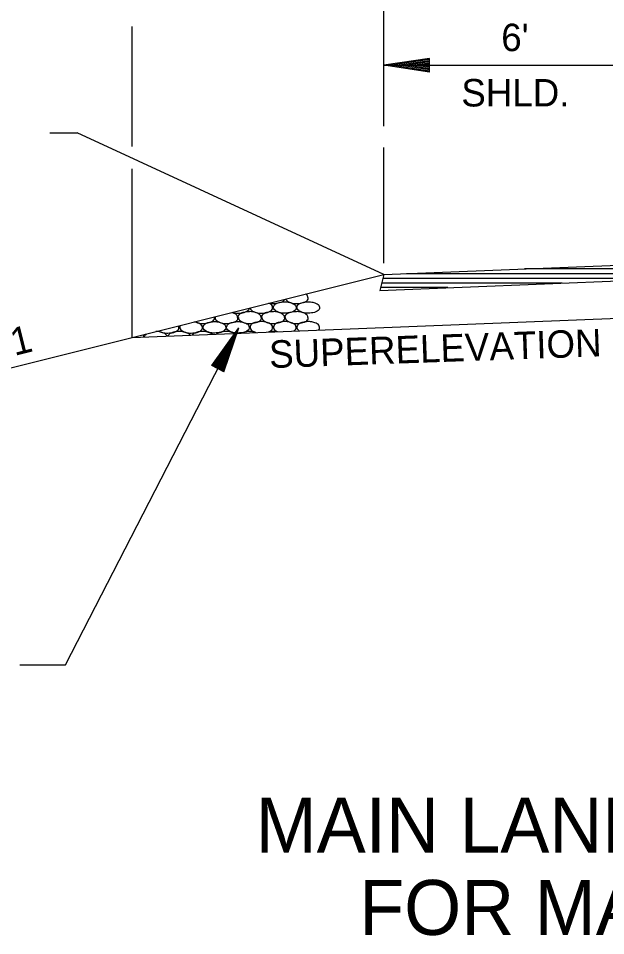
# Model space of a CAD drawing. Extents: x 1955768 to 1955917, y 566446 to 566546.
# Drawn here: x 1955818.19 to 1955831.02, y 566451.32 to 566471.36 of the extents above; entities that cross this region are included whole.
import ezdxf

# ---------------------------------------------------------------- set-up
doc = ezdxf.new("R2010")
doc.units = 0
doc.layers.add('R_Border', color=7, linetype='Continuous')
doc.layers.add('R_Grid', color=7, linetype='Continuous')

msp = doc.modelspace()

# ---------------------------------------------------------------- linework, layer by layer
at = {"layer": 'R_Border'}
for p, q in [((1955818.875, 566468.864), (1955819.475, 566468.864)), ((1955826.173, 566465.764), (1955847.173, 566466.604)), ((1955826.087, 566465.42), (1955847.339, 566466.271)), ((1955812.527, 566462.353), (1955826.173, 566465.764)), ((1955826.173, 566465.764), (1955826.087, 566465.42)), ((1955820.673, 566464.389), (1955847.173, 566465.449))]:
    msp.add_line(p, q, dxfattribs=at)
at = {"layer": 'R_Grid'}
for p, q in [((1955826.173, 566469.009), (1955826.173, 566476.637)), ((1955820.673, 566468.563), (1955820.673, 566471.186)), ((1955827.173, 566470.486), (1955826.173, 566470.336)), ((1955827.173, 566470.461), (1955826.34, 566470.336)), ((1955827.173, 566470.186), (1955827.173, 566470.486)), ((1955826.173, 566470.336), (1955832.173, 566470.336)), ((1955827.173, 566470.186), (1955826.173, 566470.336)), ((1955827.173, 566470.211), (1955826.34, 566470.336)), ((1955827.173, 566470.436), (1955826.512, 566470.336)), ((1955827.173, 566470.237), (1955826.512, 566470.336)), ((1955827.173, 566470.411), (1955826.678, 566470.336)), ((1955827.173, 566470.262), (1955826.678, 566470.336)), ((1955827.173, 566470.385), (1955826.848, 566470.336)), ((1955827.173, 566470.288), (1955826.848, 566470.336)), ((1955827.173, 566470.36), (1955827.015, 566470.336)), ((1955827.173, 566470.313), (1955827.015, 566470.336)), ((1955826.173, 566465.764), (1955819.475, 566468.864)), ((1955826.173, 566466.014), (1955826.173, 566468.54)), ((1955820.673, 566464.389), (1955820.673, 566468.075)), ((1955837.754, 566465.887), (1955829.247, 566465.887)), ((1955832.605, 566465.681), (1955826.152, 566465.681)), ((1955835.105, 566465.781), (1955826.673, 566465.781)), ((1955827.577, 566465.48), (1955826.102, 566465.48)), ((1955830.077, 566465.58), (1955826.127, 566465.58)), ((1955822.414, 566463.78), (1955823.005, 566464.601)), ((1955822.436, 566463.769), (1955822.928, 566464.452)), ((1955822.658, 566463.654), (1955822.928, 566464.452)), ((1955822.681, 566463.643), (1955823.005, 566464.601)), ((1955822.459, 566463.757), (1955822.849, 566464.299)), ((1955822.636, 566463.666), (1955822.849, 566464.299)), ((1955822.481, 566463.746), (1955822.773, 566464.151)), ((1955822.614, 566463.677), (1955822.773, 566464.151)), ((1955822.504, 566463.734), (1955822.696, 566464.001)), ((1955822.526, 566463.722), (1955822.619, 566463.852)), ((1955822.568, 566463.701), (1955822.619, 566463.852)), ((1955822.59, 566463.689), (1955822.696, 566464.001)), ((1955822.681, 566463.643), (1955822.414, 566463.78))]:
    msp.add_line(p, q, dxfattribs=at)
msp.add_lwpolyline([(1955818.222, 566457.238), (1955819.222, 566457.238), (1955823.005, 566464.601)], dxfattribs=at)
for points in [[(1955824.267, 566465.13), (1955824.27, 566465.13), (1955824.294, 566465.13), (1955824.343, 566465.134), (1955824.407, 566465.153), (1955824.472, 566465.17), (1955824.518, 566465.209), (1955824.525, 566465.245), (1955824.525, 566465.258), (1955824.525, 566465.26)], [(1955824.517, 566465.26), (1955824.517, 566465.261), (1955824.517, 566465.279), (1955824.505, 566465.313), (1955824.48, 566465.331), (1955824.468, 566465.338)], [(1955823.254, 566465.034), (1955823.257, 566465.017), (1955823.275, 566464.989), (1955823.316, 566464.96), (1955823.375, 566464.935), (1955823.44, 566464.92), (1955823.506, 566464.92), (1955823.567, 566464.926), (1955823.636, 566464.93), (1955823.697, 566464.966), (1955823.745, 566464.998), (1955823.75, 566465.049), (1955823.734, 566465.1), (1955823.698, 566465.122), (1955823.674, 566465.133), (1955823.664, 566465.137)], [(1955823.67, 566465.138), (1955823.686, 566465.135), (1955823.714, 566465.13), (1955823.742, 566465.13), (1955823.755, 566465.13)], [(1955823.755, 566465.13), (1955823.758, 566465.13), (1955823.782, 566465.13), (1955823.831, 566465.134), (1955823.895, 566465.153), (1955823.96, 566465.17), (1955823.997, 566465.201), (1955824.006, 566465.222), (1955824.006, 566465.222)], [(1955824.011, 566465.17), (1955823.982, 566465.171), (1955823.914, 566465.162), (1955823.822, 566465.137), (1955823.771, 566465.09), (1955823.759, 566465.035), (1955823.784, 566464.991), (1955823.828, 566464.96), (1955823.887, 566464.935), (1955823.952, 566464.92), (1955824.018, 566464.92), (1955824.079, 566464.926), (1955824.148, 566464.93), (1955824.209, 566464.966), (1955824.257, 566464.998), (1955824.262, 566465.049), (1955824.246, 566465.1), (1955824.207, 566465.124), (1955824.159, 566465.145), (1955824.113, 566465.159), (1955824.062, 566465.171), (1955824.03, 566465.172), (1955824.011, 566465.17)], [(1955824.03, 566465.228), (1955824.035, 566465.218), (1955824.052, 566465.197), (1955824.09, 566465.17), (1955824.149, 566465.145), (1955824.212, 566465.13), (1955824.254, 566465.13), (1955824.267, 566465.13)], [(1955824.523, 566465.17), (1955824.494, 566465.171), (1955824.426, 566465.162), (1955824.334, 566465.137), (1955824.283, 566465.09), (1955824.271, 566465.035), (1955824.296, 566464.991), (1955824.34, 566464.96), (1955824.399, 566464.935), (1955824.464, 566464.92), (1955824.53, 566464.92), (1955824.591, 566464.926), (1955824.66, 566464.93), (1955824.721, 566464.966), (1955824.769, 566464.998), (1955824.774, 566465.049), (1955824.758, 566465.1), (1955824.719, 566465.124), (1955824.671, 566465.145), (1955824.625, 566465.159), (1955824.574, 566465.171), (1955824.542, 566465.172), (1955824.523, 566465.17)], [(1955822.981, 566464.826), (1955822.981, 566464.827), (1955822.981, 566464.845), (1955822.967, 566464.883), (1955822.927, 566464.908), (1955822.889, 566464.924), (1955822.867, 566464.932), (1955822.858, 566464.935)], [(1955822.865, 566464.937), (1955822.89, 566464.929), (1955822.931, 566464.92), (1955822.994, 566464.92), (1955823.055, 566464.926), (1955823.124, 566464.93), (1955823.185, 566464.966), (1955823.229, 566464.995), (1955823.235, 566465.023), (1955823.236, 566465.03)], [(1955823.237, 566464.954), (1955823.208, 566464.955), (1955823.14, 566464.946), (1955823.051, 566464.92), (1955822.994, 566464.872), (1955822.988, 566464.838), (1955822.987, 566464.827), (1955822.987, 566464.826)], [(1955823.243, 566464.954), (1955823.241, 566464.954), (1955823.239, 566464.954), (1955823.237, 566464.954)], [(1955823.493, 566464.826), (1955823.493, 566464.827), (1955823.493, 566464.845), (1955823.479, 566464.883), (1955823.439, 566464.908), (1955823.391, 566464.929), (1955823.345, 566464.943), (1955823.294, 566464.955), (1955823.262, 566464.956), (1955823.243, 566464.954)], [(1955823.749, 566464.954), (1955823.72, 566464.955), (1955823.652, 566464.946), (1955823.563, 566464.92), (1955823.506, 566464.872), (1955823.5, 566464.838), (1955823.499, 566464.827), (1955823.499, 566464.826)], [(1955823.755, 566464.954), (1955823.753, 566464.954), (1955823.751, 566464.954), (1955823.749, 566464.954)], [(1955824.005, 566464.826), (1955824.005, 566464.827), (1955824.005, 566464.845), (1955823.991, 566464.883), (1955823.951, 566464.908), (1955823.903, 566464.929), (1955823.857, 566464.943), (1955823.806, 566464.955), (1955823.774, 566464.956), (1955823.755, 566464.954)], [(1955824.261, 566464.954), (1955824.232, 566464.955), (1955824.164, 566464.946), (1955824.075, 566464.92), (1955824.018, 566464.872), (1955824.012, 566464.838), (1955824.011, 566464.827), (1955824.011, 566464.826)], [(1955824.267, 566464.954), (1955824.265, 566464.954), (1955824.263, 566464.954), (1955824.261, 566464.954)], [(1955824.517, 566464.826), (1955824.517, 566464.827), (1955824.517, 566464.845), (1955824.503, 566464.883), (1955824.463, 566464.908), (1955824.415, 566464.929), (1955824.369, 566464.943), (1955824.318, 566464.955), (1955824.286, 566464.956), (1955824.267, 566464.954)], [(1955821.256, 566464.535), (1955821.258, 566464.534), (1955821.278, 566464.522), (1955821.327, 566464.501), (1955821.392, 566464.486), (1955821.458, 566464.486), (1955821.519, 566464.492), (1955821.588, 566464.496), (1955821.649, 566464.532), (1955821.697, 566464.564), (1955821.702, 566464.609), (1955821.696, 566464.633), (1955821.692, 566464.644)], [(1955821.727, 566464.652), (1955821.725, 566464.649), (1955821.718, 566464.636), (1955821.711, 566464.601), (1955821.736, 566464.557), (1955821.78, 566464.526), (1955821.839, 566464.501), (1955821.904, 566464.486), (1955821.97, 566464.486), (1955822.031, 566464.492), (1955822.1, 566464.496), (1955822.161, 566464.532), (1955822.209, 566464.564), (1955822.214, 566464.615), (1955822.198, 566464.666), (1955822.159, 566464.69), (1955822.111, 566464.711), (1955822.071, 566464.723), (1955822.045, 566464.729), (1955822.04, 566464.731)], [(1955822.051, 566464.734), (1955822.066, 566464.727), (1955822.108, 566464.71), (1955822.164, 566464.696), (1955822.206, 566464.696), (1955822.219, 566464.696)], [(1955822.219, 566464.696), (1955822.222, 566464.696), (1955822.246, 566464.696), (1955822.295, 566464.7), (1955822.359, 566464.719), (1955822.424, 566464.736), (1955822.47, 566464.775), (1955822.477, 566464.811), (1955822.477, 566464.824), (1955822.477, 566464.826)], [(1955822.475, 566464.736), (1955822.446, 566464.737), (1955822.378, 566464.728), (1955822.286, 566464.703), (1955822.235, 566464.656), (1955822.223, 566464.601), (1955822.248, 566464.557), (1955822.292, 566464.526), (1955822.351, 566464.501), (1955822.416, 566464.486), (1955822.482, 566464.486), (1955822.543, 566464.492), (1955822.612, 566464.496), (1955822.673, 566464.532), (1955822.721, 566464.564), (1955822.726, 566464.615), (1955822.71, 566464.666), (1955822.671, 566464.69), (1955822.623, 566464.711), (1955822.577, 566464.725), (1955822.526, 566464.737), (1955822.494, 566464.738), (1955822.475, 566464.736)], [(1955822.487, 566464.826), (1955822.487, 566464.824), (1955822.486, 566464.802), (1955822.509, 566464.768), (1955822.554, 566464.736), (1955822.613, 566464.711), (1955822.676, 566464.696), (1955822.718, 566464.696), (1955822.731, 566464.696)], [(1955822.731, 566464.696), (1955822.734, 566464.696), (1955822.758, 566464.696), (1955822.807, 566464.7), (1955822.871, 566464.719), (1955822.936, 566464.736), (1955822.982, 566464.775), (1955822.989, 566464.811), (1955822.989, 566464.824), (1955822.989, 566464.826)], [(1955822.987, 566464.736), (1955822.958, 566464.737), (1955822.89, 566464.728), (1955822.798, 566464.703), (1955822.747, 566464.656), (1955822.735, 566464.601), (1955822.76, 566464.557), (1955822.804, 566464.526), (1955822.863, 566464.501), (1955822.928, 566464.486), (1955822.994, 566464.486), (1955823.055, 566464.492), (1955823.124, 566464.496), (1955823.185, 566464.532), (1955823.233, 566464.564), (1955823.238, 566464.615), (1955823.222, 566464.666), (1955823.183, 566464.69), (1955823.135, 566464.711), (1955823.089, 566464.725), (1955823.038, 566464.737), (1955823.006, 566464.738), (1955822.987, 566464.736)], [(1955822.999, 566464.826), (1955822.999, 566464.824), (1955822.998, 566464.802), (1955823.021, 566464.768), (1955823.066, 566464.736), (1955823.125, 566464.711), (1955823.188, 566464.696), (1955823.23, 566464.696), (1955823.243, 566464.696)], [(1955823.243, 566464.696), (1955823.246, 566464.696), (1955823.27, 566464.696), (1955823.319, 566464.7), (1955823.383, 566464.719), (1955823.448, 566464.736), (1955823.494, 566464.775), (1955823.501, 566464.811), (1955823.501, 566464.824), (1955823.501, 566464.826)], [(1955823.499, 566464.736), (1955823.47, 566464.737), (1955823.402, 566464.728), (1955823.31, 566464.703), (1955823.259, 566464.656), (1955823.247, 566464.601), (1955823.272, 566464.557), (1955823.316, 566464.526), (1955823.351, 566464.51), (1955823.378, 566464.502), (1955823.382, 566464.5)], [(1955823.657, 566464.511), (1955823.669, 566464.516), (1955823.702, 566464.536), (1955823.745, 566464.564), (1955823.75, 566464.615), (1955823.734, 566464.666), (1955823.695, 566464.69), (1955823.647, 566464.711), (1955823.601, 566464.725), (1955823.55, 566464.737), (1955823.518, 566464.738), (1955823.499, 566464.736)], [(1955823.511, 566464.826), (1955823.511, 566464.824), (1955823.51, 566464.802), (1955823.533, 566464.768), (1955823.578, 566464.736), (1955823.637, 566464.711), (1955823.7, 566464.696), (1955823.742, 566464.696), (1955823.755, 566464.696)], [(1955823.755, 566464.696), (1955823.758, 566464.696), (1955823.782, 566464.696), (1955823.831, 566464.7), (1955823.895, 566464.719), (1955823.96, 566464.736), (1955824.006, 566464.775), (1955824.013, 566464.811), (1955824.013, 566464.824), (1955824.013, 566464.826)], [(1955824.011, 566464.736), (1955823.982, 566464.737), (1955823.914, 566464.728), (1955823.822, 566464.703), (1955823.771, 566464.656), (1955823.759, 566464.601), (1955823.784, 566464.557), (1955823.816, 566464.533), (1955823.836, 566464.523), (1955823.845, 566464.519)], [(1955824.208, 566464.533), (1955824.225, 566464.545), (1955824.258, 566464.566), (1955824.262, 566464.615), (1955824.246, 566464.666), (1955824.207, 566464.69), (1955824.159, 566464.711), (1955824.113, 566464.725), (1955824.062, 566464.737), (1955824.03, 566464.738), (1955824.011, 566464.736)], [(1955824.023, 566464.826), (1955824.023, 566464.824), (1955824.022, 566464.802), (1955824.045, 566464.768), (1955824.09, 566464.736), (1955824.149, 566464.711), (1955824.212, 566464.696), (1955824.254, 566464.696), (1955824.267, 566464.696)], [(1955824.267, 566464.696), (1955824.27, 566464.696), (1955824.294, 566464.696), (1955824.343, 566464.7), (1955824.407, 566464.719), (1955824.472, 566464.736), (1955824.518, 566464.775), (1955824.525, 566464.811), (1955824.525, 566464.824), (1955824.525, 566464.826)], [(1955824.523, 566464.736), (1955824.494, 566464.737), (1955824.426, 566464.728), (1955824.334, 566464.703), (1955824.283, 566464.656), (1955824.271, 566464.601), (1955824.293, 566464.561), (1955824.314, 566464.543), (1955824.322, 566464.538)], [(1955824.747, 566464.555), (1955824.754, 566464.561), (1955824.771, 566464.578), (1955824.774, 566464.615), (1955824.758, 566464.666), (1955824.719, 566464.69), (1955824.671, 566464.711), (1955824.625, 566464.725), (1955824.574, 566464.737), (1955824.542, 566464.738), (1955824.523, 566464.736)], [(1955820.932, 566464.402), (1955820.931, 566464.416), (1955820.924, 566464.434), (1955820.914, 566464.447), (1955820.912, 566464.449)], [(1955820.985, 566464.467), (1955820.968, 566464.456), (1955820.949, 566464.436), (1955820.941, 566464.41), (1955820.94, 566464.403)], [(1955821.44, 566464.423), (1955821.437, 566464.429), (1955821.424, 566464.454), (1955821.391, 566464.474), (1955821.343, 566464.495), (1955821.297, 566464.509), (1955821.246, 566464.521), (1955821.214, 566464.522), (1955821.195, 566464.52)], [(1955821.701, 566464.52), (1955821.672, 566464.521), (1955821.604, 566464.512), (1955821.515, 566464.486), (1955821.471, 566464.447), (1955821.459, 566464.424), (1955821.458, 566464.423)], [(1955821.707, 566464.52), (1955821.705, 566464.52), (1955821.703, 566464.52), (1955821.701, 566464.52)], [(1955821.941, 566464.443), (1955821.93, 566464.458), (1955821.903, 566464.474), (1955821.855, 566464.495), (1955821.809, 566464.509), (1955821.758, 566464.521), (1955821.726, 566464.522), (1955821.707, 566464.52)], [(1955822.213, 566464.52), (1955822.184, 566464.521), (1955822.116, 566464.512), (1955822.037, 566464.488), (1955821.995, 566464.457), (1955821.985, 566464.444)], [(1955822.219, 566464.52), (1955822.217, 566464.52), (1955822.215, 566464.52), (1955822.213, 566464.52)], [(1955822.433, 566464.462), (1955822.427, 566464.467), (1955822.407, 566464.478), (1955822.367, 566464.495), (1955822.321, 566464.509), (1955822.27, 566464.521), (1955822.238, 566464.522), (1955822.219, 566464.52)], [(1955822.725, 566464.52), (1955822.696, 566464.521), (1955822.628, 566464.512), (1955822.562, 566464.491), (1955822.525, 566464.469), (1955822.521, 566464.466)], [(1955822.731, 566464.52), (1955822.729, 566464.52), (1955822.727, 566464.52), (1955822.725, 566464.52)], [(1955822.911, 566464.481), (1955822.902, 566464.486), (1955822.874, 566464.496), (1955822.833, 566464.509), (1955822.782, 566464.521), (1955822.75, 566464.522), (1955822.731, 566464.52)], [(1955823.237, 566464.52), (1955823.208, 566464.521), (1955823.151, 566464.513), (1955823.099, 566464.498), (1955823.076, 566464.488)], [(1955823.243, 566464.52), (1955823.241, 566464.52), (1955823.239, 566464.52), (1955823.237, 566464.52)], [(1955823.373, 566464.5), (1955823.361, 566464.504), (1955823.337, 566464.511), (1955823.294, 566464.521), (1955823.262, 566464.522), (1955823.243, 566464.52)], [(1955823.749, 566464.52), (1955823.722, 566464.521), (1955823.695, 566464.517), (1955823.668, 566464.512)], [(1955823.755, 566464.52), (1955823.753, 566464.52), (1955823.751, 566464.52), (1955823.749, 566464.52)], [(1955823.815, 566464.518), (1955823.814, 566464.518), (1955823.794, 566464.521), (1955823.774, 566464.522), (1955823.755, 566464.52)]]:
    msp.add_open_spline(points, degree=3, dxfattribs=at)

# ---------------------------------------------------------------- texts
at = {"layer": 'R_Border'}
for s, height, p in [("6'", 0.6, (1955828.742, 566470.646)), ('SHLD.', 0.6, (1955827.87, 566469.437)), ('MAIN LANE TEMPORARY CROSSOVER', 1.2, (1955823.373, 566453.138)), ('FOR MAINTENANCE OF TRAFFIC', 1.2, (1955825.64, 566451.338))]:
    msp.add_text(s, height=height, dxfattribs=at).set_placement(p)
for s, rotation, p in [('4:1', 14.1451, (1955817.454, 566463.822)), ('SUPERELEVATION', 2.0327, (1955823.68, 566463.721))]:
    msp.add_text(s, height=0.6, rotation=rotation, dxfattribs=at).set_placement(p)

doc.saveas('drawing.dxf')
